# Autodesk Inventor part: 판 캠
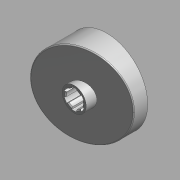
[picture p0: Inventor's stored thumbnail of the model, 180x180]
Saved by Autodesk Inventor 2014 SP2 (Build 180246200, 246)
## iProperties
Created: 2015-11
Part Number: 판 캠
Document SubType Name: 모델링
Designer: mdu
Material: 강철, 연강
Density: 7.86 g/cm^3
Appearance: 알루미늄 - 평지
Mass: 682.455 g
Surface Area: 331.303 cm^2
Volume: 86.8264 cm^3
변환 표준: STEP AP214IS
파일 이름: C:\Users\SeoGD\Desktop\?쒗뿕\??stp
전처리기: Build: 253, Release: 2010 SP1 - Date: Wed 07/29/2009
전송 단위: 밀리미터
불확실성: 0.01
Author: mdu
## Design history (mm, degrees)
node "작업 평면4"
sketch "스케치1"
  geometry: C1 r 44.5 at (0, 0); 1 further point
  constraints: 1 centre point, 1 coincident
  dimensions: "d25" = 89 diameter of C1
extrude "돌출1" new body sketch "스케치1" distance "d1" = 40; taper "d2" = 0 deg
sketch "스케치2"
  geometry: L1 (-44.5, 15)-(44.5, 38.847); L2 (-44.5, 0)-(-44.5, 40) reference; L3 (-44.5, 40)-(44.5, 40) reference; L4 (44.5, 0)-(44.5, 40) reference; 1 further point
  constraints: 2 end point, 2 point on line
  dimensions: "d26" = 15 distance of L2.start L1.start; "d27" = 75 deg angle of L1 L2
extrude "돌출2" cut sketch "스케치2" stored distance "d5" = 40; taper "d6" = 0 deg
node "작업 평면1"
sketch "스케치3"
  geometry: C1 r 13 at (0, 0); 1 further point
  constraints: 1 centre point, 1 coincident
  dimensions: "d9" = 26 diameter of C1
extrude "돌출3" join sketch "스케치3" distance "d10" = 38; taper "d11" = 0 deg
hole "구멍1" diameter "d14" = 18; stored, may be unused: countersink angle "d18" = 90 deg, drill point angle "d20" = 118 deg; dims "d12" = 10, "d13" = 10, "d15" = 6, "d16" = 4, "d17" = 2, "d19" = 8
feature "쉘2" dims "d29" = 5
sketch "스케치6"
  geometry: C1 r 17.5 at (0, 0); C2 r 14 at (0, 0) reference; 1 further point
  constraints: 1 centre point, 1 coincident
  dimensions: "d28" = 35 diameter of C1
extrude "돌출4" join sketch "스케치6" stored distance "d30" = 38; taper "d31" = 0 deg
fillet "모깎기1" dims "d32" = 3
chamfer "모따기1" distance "d21" = 1; stored, may be unused: second distance "d22" = 2, angle "d23" = 45 deg
sketch "스케치7"
  geometry: L1 (-12.374, 12.374)-(-27.931, 27.931); A1 r 39.5 centre (0, 0) between (-27.931, 27.931) and (0, 39.5) reference; 2 further points
  constraints: 2 end point, 2 point on circle, 1 point on line, 1 vertical alignment, 2 other
  dimensions: "d33" = 45 deg dimension on point (0, 0) L1.start A1.end
feature "리브1" sketch "스케치7" dims "d34" = 5, "d35" = 1, "d36" = 0
fillet "모깎기2" dims "d37" = 3
sketch "스케치8"
  geometry: L1 (2.5, 10.712)-(2.5, 8.646); L2 (-2.5, 10.712)-(-2.5, 8.646); A1 r 11 centre (0, 0) between (2.5, 10.712) and (-2.5, 10.712); A2 r 9 centre (0, 0) between (2.5, 8.646) and (-2.5, 8.646) reference; 1 further point
  constraints: 4 end point, 4 point on circle, 2 parallel, 1 centre point, 1 coincident, 1 vertical
  dimensions: "d41" = 22 diameter of A1; "d42" = 5 distance between parallel lines of L1 L2
extrude "돌출5" cut sketch "스케치8" stored distance "d43" = 38; taper "d44" = 0 deg
fillet "모깎기3" dims "d48" = 1
node "솔리드1"
node "솔리드 본체"
node "곡면 본체"
pattern_circular "원형 패턴1" dims angle "d39" = 360 deg
pattern_circular "원형 패턴2" dims angle "d46" = 360 deg
node "솔리드2"
